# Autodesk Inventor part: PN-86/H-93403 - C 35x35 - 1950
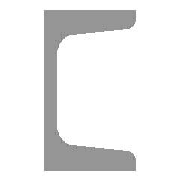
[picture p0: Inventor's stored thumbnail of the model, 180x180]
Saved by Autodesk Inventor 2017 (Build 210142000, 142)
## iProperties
Created: 2016-02
Part Number: PN-86/H-93403 - C 35x35 - 1950
Material: Stal, miękka
Description: Ceownik
Document SubType Name: Modeling
Standard: PN
Designer: X
Standards Organization: PN
Language: pl-PL
Size Designation: C 35x35
Categories: <MemberInstance><Categories><Category DisplayName="Kształtowniki konstrukcyjne" InternalName="089c4875-fa83-4c05-b084-43b9cc11f5ed" Mnemonic="GRDR"><CategoryPar
Stock Number: C 35x35
Density: 7.85 g/cm^3
Appearance: Częściowo polerowana
_CCFamilyMember: 10
_CCFamilyDisplayName: PN-86/H-93403 - Ceownik
_FrameMemberDoc: Frame Member File
_Version: 15.0.0
_GetPNFromCC: 1
G_L: 1950,000 mm
G_W: 35,000 mm
G_H: 35,000 mm
IsCustomPart: 1
Author: X
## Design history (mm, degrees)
node "Płaszczyzna początkowa"
node "Płaszczyzna końcowa"
sketch "Szkic"
  geometry: L1 (0, 0)-(0, 17.5); L2 (0, 17.5)-(35, 17.5); L3 (35, 17.5)-(35, 15.47); L4 (32.239, 12.479)-(10.522, 10.742); L5 (5, 4.761)-(5, 0); L6 (5, 0)-(0, 0); L7 (20, 17.5)-(20, 11.5); L8 (35, 12.7)-(35, 11.5); L9 (35, 11.5)-(20, 11.5); L10 (0, 15)-(0, -27); L11 (-5.539, 0)-(16.007, 0); L12 (0, 0)-(0, -17.5); L13 (0, -17.5)-(35, -17.5); L14 (35, -17.5)-(35, -15.47); L15 (32.239, -12.479)-(10.522, -10.742); L16 (5, -4.761)-(5, 0); L17 (0, 26.4)-(0, -35.9) reference; L18 (-13.764, 0)-(43.809, 0) reference; A1 r 6 centre (11, 4.761) between (10.522, 10.742) and (5, 4.761); A2 r 6 centre (11, -4.761) between (5, -4.761) and (10.522, -10.742); A3 r 3 centre (32, 15.47) between (32.239, 12.479) and (35, 15.47); A4 r 3 centre (32, -15.47) between (35, -15.47) and (32.239, -12.479); 5 further points
  constraints: 32 end point, 12 point on line, 8 point on circle, 8 tangent, 6 symmetric about line, 4 centre point, 4 parallel, 3 collinear, 3 perpendicular, 2 equal radius, 5 other
  dimensions: "d0" = 5 distance between parallel lines of L1 L5 (= G_T); "d1" = 17.5 distance between parallel lines of L6 L2 (= 0.5 x G_H); "d2" = 35 distance between parallel lines of L3 L1 (= G_W); "d3" = 6 distance of L2.end L8.end (= G_T1); "d4" = 15 distance of L7.start L2.end (= G_C); "d5" = 1.2 distance of L8.start L8.end (computed from G_NG, G_C); "d23" = 6 radius of A1 (= G_IR); "d24" = 3 radius of A3 (= G_ER); "d25" = 0 distance between parallel lines of L10 L12 (computed from ex)
extrude "Bryła" new body sketch "Szkic" stored distance "d6" = 1950 (= G_L); taper "d7" = 0 deg
node "Driven Length"
  sketch "Sketch3"
    geometry: L1 (0, 0)-(10, 0) reference
    constraints: 2 end point, 1 horizontal
  workplane "Work Plane3"
  sketch "Sketch4"
    geometry: L1 (-2, 0)-(12, 0) reference; L2 (-2, 1950)-(12, 1950) reference
    dimensions: "d29" = 1950 distance between parallel lines of L1 L2 (derived)
body "Solid1"
other parameters: "G_W" = 35 [user parameter; used in 1 equation term], "G_H" = 35 [user parameter; used in 1 equation term], "G_T" = 5 [user parameter; used in 1 equation term], "G_T1" = 6 [user parameter; used in 1 equation term], "G_NG" = 0.8 [user parameter; used in 1 equation term], "G_ER" = 3 [user parameter; used in 1 equation term], "G_IR" = 6 [user parameter; used in 1 equation term], "G_C" = 15 [user parameter; used in 2 equation terms], "G_L" = 1950 (= d29) [user parameter; used in 1 equation term], "ex" = 0 [user parameter; used in 1 equation term], "G_OFFSET_START" = 0 [user parameter; used in 1 equation term], "G_OFFSET_END" = 0 [user parameter; used in 1 equation term], "d26" = 0 (computed from G_OFFSET_START), "d28" = 90 deg
